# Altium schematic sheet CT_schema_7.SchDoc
size 365 x 245 mm
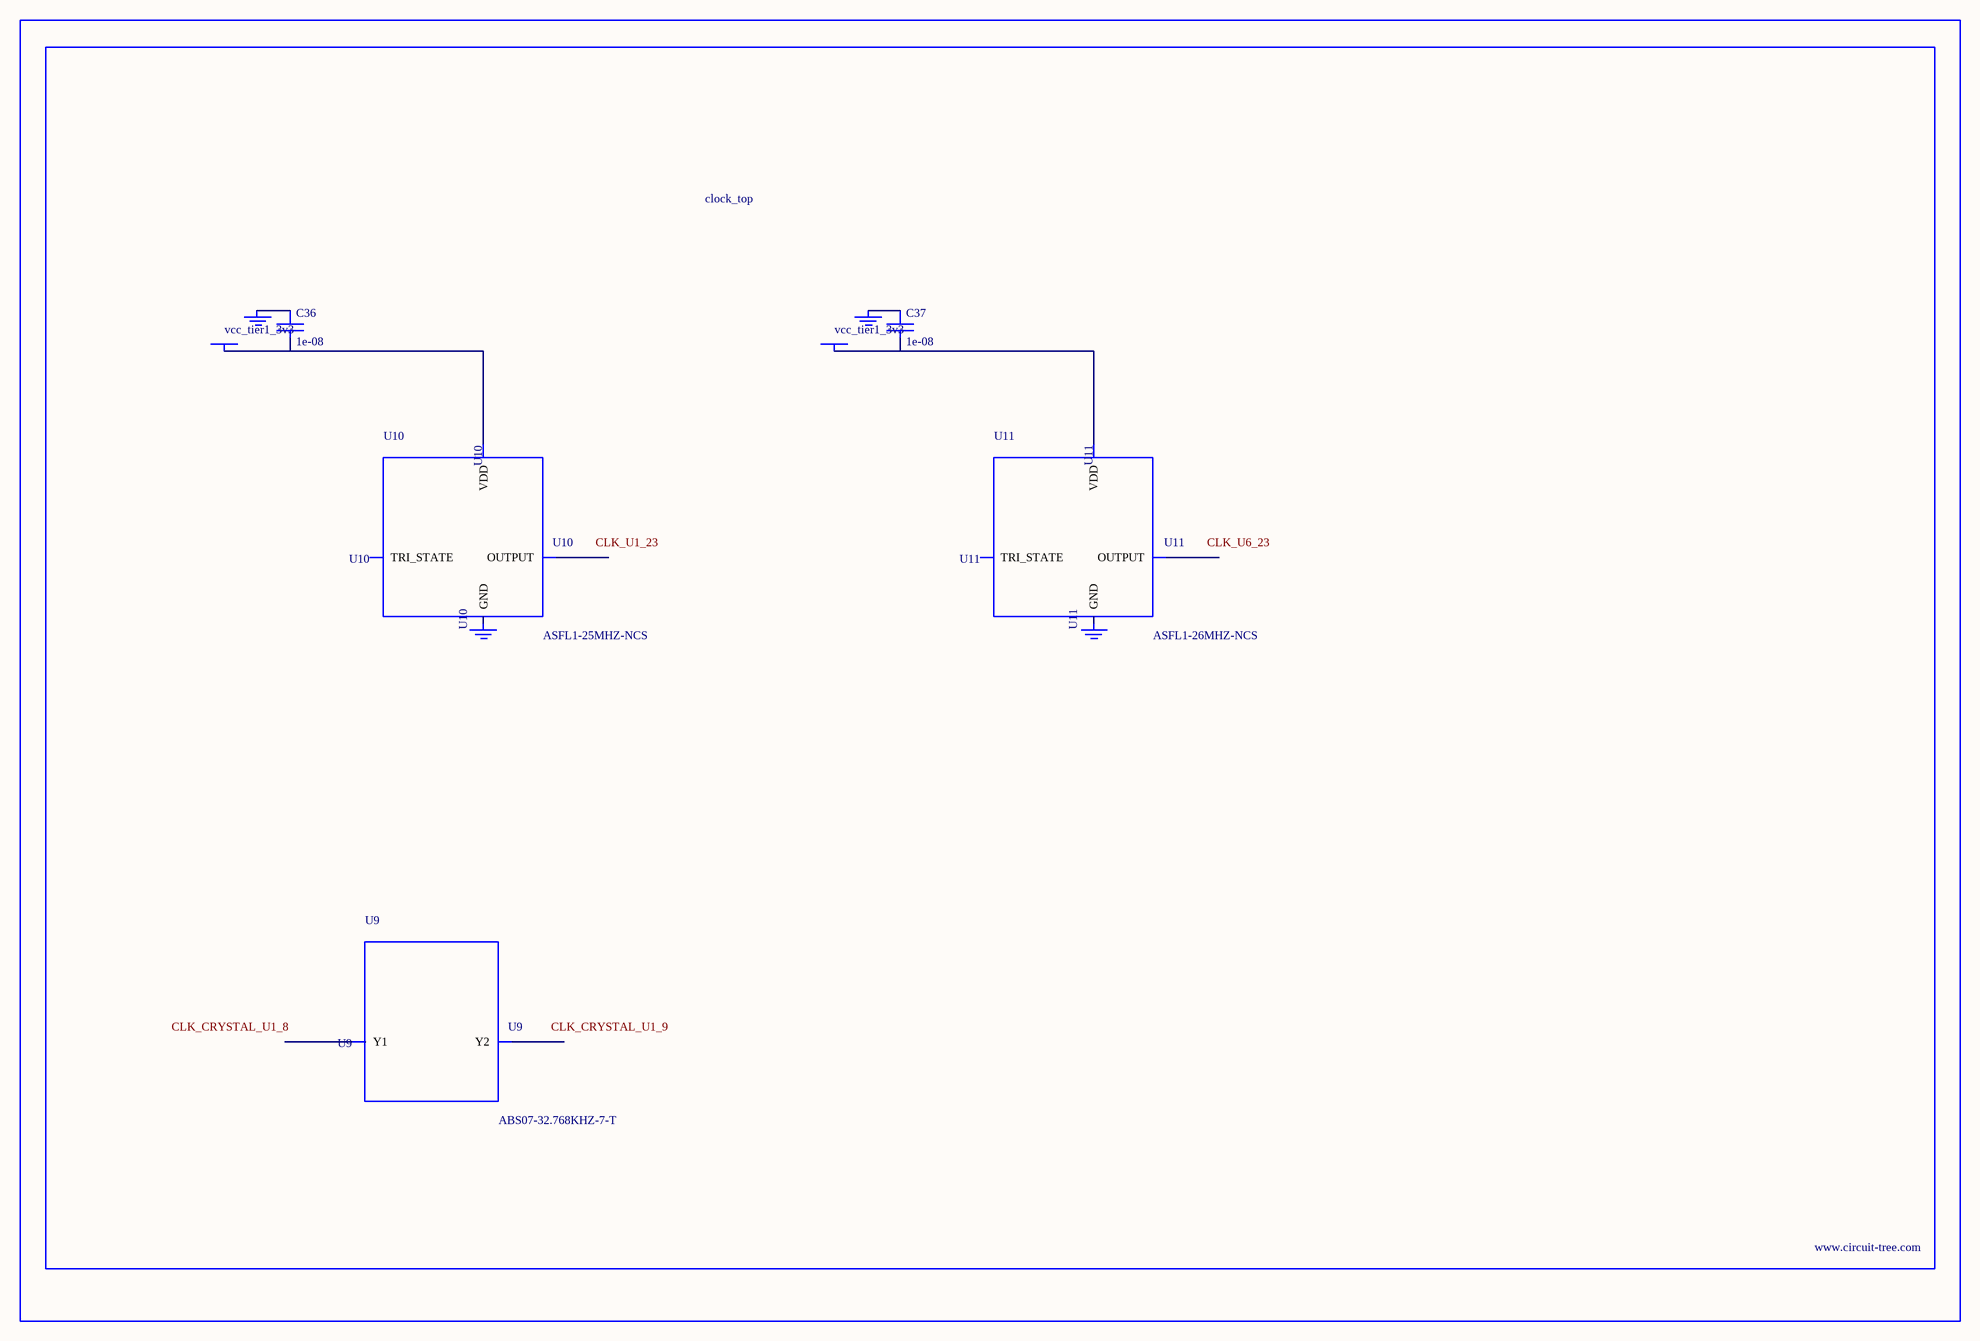
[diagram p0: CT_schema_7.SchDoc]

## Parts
BORDER6  (no value)
C36  1e-08  [C0402]
C37  1e-08  [C0402]
GND_INSTANCE_6_0  (no value)
GND_INSTANCE_6_1  (no value)
GND_INSTANCE_6_2  (no value)
GND_INSTANCE_6_3  (no value)
POWER_INSTANCE_6_0  vcc_tier1_3v3
POWER_INSTANCE_6_1  vcc_tier1_3v3
U9  ABS07-32.768KHZ-7-T  [ABS07-32.768KHZ-7-T]
U10  ASFL1-25MHZ-NCS  [ASFL1]
U11  ASFL1-26MHZ-NCS  [ASFL1]

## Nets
NetC36_1: C36.1 GND_INSTANCE_6_0.0(GND)
NetC36_2: C36.2 POWER_INSTANCE_6_0.0(PWR) U10.4(VDD)
NetC37_1: C37.1 GND_INSTANCE_6_2.0(GND)
NetC37_2: C37.2 POWER_INSTANCE_6_1.0(PWR) U11.4(VDD)

Not connected (* = marked no-connect by the designer): GND_INSTANCE_6_1 0(GND); GND_INSTANCE_6_3 0(GND); U9 1(Y1) 2(Y2); U10 1(TRI_STATE) 2(GND) 3(OUTPUT); U11 1(TRI_STATE) 2(GND) 3(OUTPUT)

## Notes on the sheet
- Labels drawn without touching a wire or pin: CLK_CRYSTAL_U1_8, CLK_CRYSTAL_U1_9, CLK_U1_23, CLK_U6_23

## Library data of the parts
BORDER6 = BORDER_PAGE6
C36 C37 = C0402C103K3RAC
GND_INSTANCE_6_0-GND_INSTANCE_6_3 = GND
POWER_INSTANCE_6_0 POWER_INSTANCE_6_1 = PWR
